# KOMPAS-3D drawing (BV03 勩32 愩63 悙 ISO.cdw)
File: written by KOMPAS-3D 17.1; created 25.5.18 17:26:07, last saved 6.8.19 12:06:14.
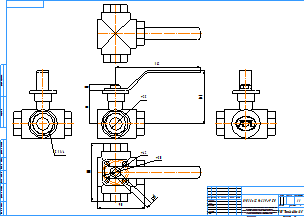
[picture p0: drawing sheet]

Sheet 1: A2, landscape

Title block, sheet 1: name: BV03 Ду32 Ру63 Р/Р ISO; material: Сталь 20  ГОСТ 1050-88; sheets: 1; sheet format: A2; stored path: C:\Users\kka\KOMPAS_Work\!Trash\BV3 кран трехходовой шаровой\KOMPAS 2D\BV03 Ду32 Ру63 РР ISO.cdw

Views: Проекционный вид 2, Проекционный вид 6, Проекционный вид 7, Проекционный вид 8, Проекционный вид 9
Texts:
  kka
  adl
  Рама для чертежей
  Лит-Масса-Масштаб
  Материал-Предприятие
  Масштаб
  Изм.
  Лист
  № докум.
  Подп.
  Дата
  Лит.
  Разраб.
  Пров.
  Т.контр.
  Листов
  Внимание! Данный продукт является объектом авторского права ООО «Торговый Дом АДЛ».
  Запрещается изменение, копирование, распространение
  (в том числе путем копирования на другие сайты и ресурсы в Интернете)
  или любое иное использование информации и объектов без предварительного
  согласия правообладателя (ООО «Торговый Дом АДЛ»).
  Н.контр.
  Утв.
  ООО "Торговый дом АДЛ"
  Изменение
  Номер документа
  Подпись
  Обозначение документа
  Наименование изделия
  Масса изделия по ГОСТ 2.109-73
  Порядковый номер листа
  Общее количество листов в документе
  Характер работы, выполненной лицом, подписавшим документ
  Наименование или индекс предприятия, выпускающего документ
  Инв. № подл.
  Подп. и дата
  Взам. инв. №
  Инв. № дубл.
  Инвентарный номер подлинника по ГОСТ 2.501-68
  Подпись принявшего подлинник в отдел технической документации
  Инвентарный номер подлинника, взамен которого выпущен данный подлинник
  Инвентарный номер дубликата по ГОСТ 2.502-68
  Подпись принявшего дубликат в отдел технической документации
  Справ. №
  Перв. примен.
  Обозначение документа, взамен или на основании которого выпущен данный документ
  Обозначение документа, в котором впервые записан данный документ
  Подпись лица, копировавшего чертеж
  Обозначение формата листа
  !Рама для чертежа
Dimensions and other numbers on the sheet: 162; 25; 101; 63; 11; 111; 90; 42; 50; 1:1; 1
